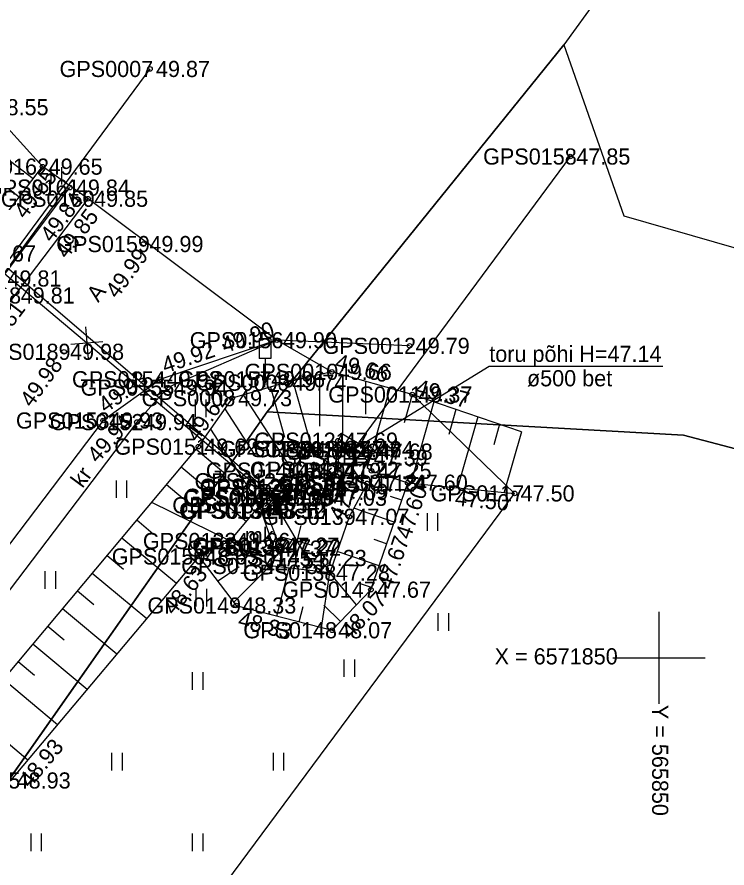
# Model space of a CAD drawing. Extents: x 563121 to 567545, y 6570841 to 6581299.
# Drawn here: x 565822.17 to 565852.95, y 6571840.89 to 6571877.77 of the extents above; entities that cross this region are included whole.
import ezdxf

# ---------------------------------------------------------------- set-up
doc = ezdxf.new("R2010")
doc.units = 0
for name, color, linetype in [('HALJASTUS', 7, 'Continuous'), ('KORGUS-EH2000', 7, 'Continuous'), ('LIIKLUS', 7, 'Continuous'), ('MOOTKORG-EH2000', 7, 'Continuous'), ('MOOTMPUNKT', 7, 'Continuous'), ('MOOTNR', 7, 'Continuous'), ('MOOTPIIR', 7, 'Continuous'), ('PIIR', 7, 'Continuous'), ('RELJEEF', 7, 'Continuous'), ('SITRASS', 7, 'Continuous'), ('TEE', 7, 'Continuous'), ('TRUUP', 7, 'Continuous'), ('VORK', 7, 'Continuous')]:
    doc.layers.add(name, color=color, linetype=linetype)

msp = doc.modelspace()

# ---------------------------------------------------------------- linework, layer by layer
at = {"layer": 'HALJASTUS'}
for p, q in [((565823.642, 6571871.268), (565823.642, 6571870.507)), ((565824.097, 6571871.268), (565824.097, 6571870.507)), ((565829.901, 6571861.198), (565829.901, 6571860.437)), ((565830.357, 6571861.198), (565830.357, 6571860.437)), ((565826.469, 6571857.691), (565826.469, 6571856.93)), ((565826.924, 6571857.691), (565826.924, 6571856.93)), ((565839.953, 6571856.265), (565839.953, 6571855.504)), ((565840.408, 6571856.265), (565840.408, 6571855.504)), ((565823.385, 6571853.755), (565823.385, 6571852.994)), ((565823.84, 6571853.755), (565823.84, 6571852.994)), ((565829.929, 6571852.992), (565829.929, 6571852.231)), ((565830.384, 6571852.992), (565830.384, 6571852.231)), ((565840.42, 6571851.929), (565840.42, 6571851.168)), ((565840.875, 6571851.929), (565840.875, 6571851.168)), ((565836.343, 6571849.932), (565836.343, 6571849.171)), ((565836.798, 6571849.932), (565836.798, 6571849.171)), ((565829.772, 6571849.381), (565829.772, 6571848.619)), ((565830.228, 6571849.381), (565830.228, 6571848.619)), ((565826.272, 6571845.881), (565826.272, 6571845.119)), ((565826.728, 6571845.881), (565826.728, 6571845.119)), ((565833.272, 6571845.881), (565833.272, 6571845.119)), ((565833.728, 6571845.881), (565833.728, 6571845.119)), ((565822.772, 6571842.381), (565822.772, 6571841.619)), ((565823.228, 6571842.381), (565823.228, 6571841.619)), ((565829.772, 6571842.381), (565829.772, 6571841.619)), ((565830.228, 6571842.381), (565830.228, 6571841.619))]:
    msp.add_line(p, q, dxfattribs=at)
at = {"layer": 'KORGUS-EH2000'}
for centre in [(565823.283, 6571871.288), (565824.465, 6571870.379), (565825.255, 6571869.896), (565827.654, 6571867.933), (565833.439, 6571863.766), (565839.194, 6571863.521), (565824.215, 6571863.263), (565835.818, 6571862.396), (565828.407, 6571862.073), (565839.307, 6571861.411), (565825.907, 6571860.285), (565827.373, 6571860.217), (565830.033, 6571859.153), (565839.111, 6571857.59), (565843.741, 6571857.127), (565836.578, 6571856.112), (565830.061, 6571854.393), (565833.143, 6571853.982), (565837.516, 6571852.954), (565831.676, 6571852.267), (565835.834, 6571851.196)]:
    msp.add_circle(centre, 0.1, dxfattribs=at)
at = {"layer": 'LIIKLUS'}
for p, q in [((565832.677, 6571863.823), (565832.677, 6571862.973)), ((565833.177, 6571863.823), (565832.677, 6571863.823)), ((565833.177, 6571863.823), (565833.177, 6571862.973)), ((565833.177, 6571862.973), (565832.677, 6571862.973)), ((565832.927, 6571862.973), (565832.927, 6571862.073)), ((565833.177, 6571862.073), (565832.927, 6571862.073))]:
    msp.add_line(p, q, dxfattribs=at)
at = {"layer": 'MOOTMPUNKT'}
for centre in [(565827.937, 6571875.522), (565846.158, 6571871.726), (565823.283, 6571871.288), (565824.465, 6571870.379), (565825.255, 6571869.896), (565827.654, 6571867.933), (565833.439, 6571863.766), (565839.194, 6571863.521), (565824.215, 6571863.263), (565835.818, 6571862.396), (565828.407, 6571862.073), (565832.927, 6571862.073), (565833.848, 6571861.926), (565828.71, 6571861.712), (565831.495, 6571861.254), (565839.307, 6571861.411), (565825.907, 6571860.285), (565827.373, 6571860.217), (565836.087, 6571859.412), (565830.033, 6571859.153), (565834.809, 6571859.05), (565836.221, 6571859.042), (565836.771, 6571859.041), (565837.589, 6571858.936), (565837.376, 6571858.673), (565836.116, 6571858.151), (565834.07, 6571858.113), (565837.54, 6571858.106), (565833.65, 6571857.652), (565833.868, 6571857.415), (565837.347, 6571857.558), (565839.111, 6571857.59), (565833.88, 6571857.348), (565835.669, 6571857.187), (565843.741, 6571857.127), (565833.216, 6571856.912), (565833.338, 6571856.981), (565835.607, 6571856.94), (565832.684, 6571856.613), (565832.924, 6571856.373), (565832.978, 6571856.386), (565836.578, 6571856.112), (565831.411, 6571855.064), (565833.546, 6571854.861), (565833.311, 6571854.735), (565833.617, 6571854.78), (565830.061, 6571854.393), (565834.731, 6571854.328), (565833.143, 6571853.982), (565835.734, 6571853.689), (565837.516, 6571852.954), (565831.676, 6571852.267), (565835.834, 6571851.196)]:
    msp.add_circle(centre, 0.1, dxfattribs=at)
at = {"layer": 'MOOTPIIR'}
msp.add_lwpolyline([(565813.701, 6571814.393), (565829.693, 6571838.184), (565843.741, 6571857.127), (565839.301, 6571861.413), (565835.818, 6571862.396), (565833.439, 6571863.766), (565825.255, 6571869.896), (565823.283, 6571871.288), (565820.939, 6571873.864)], dxfattribs=at)
at = {"layer": 'PIIR'}
for points in [[(566138.88, 6572289.1), (566071.95, 6572189.53), (566056.92, 6572168.48), (566043.44, 6572149.59), (566020.47, 6572117.41), (565845.87, 6571876.56), (565833.02, 6571860.66), (565803.59, 6571818.77), (565766.84, 6571778.8), (565712.27, 6571733.72), (565636.36, 6571689.97), (565561.65, 6571658.97), (565400, 6571600), (565315, 6571572), (565230, 6571552), (564980, 6571552), (564921.56, 6571543.26)], [(566222.72, 6571643.14), (566175.38, 6571706.88), (566160.83, 6571717.7), (566147.53, 6571725.81), (566110.96, 6571742.32), (566089.86, 6571753.57), (566023.53, 6571796.39), (565973.49, 6571828.72), (565960.44, 6571833.78), (565901.01, 6571846.54), (565851.06, 6571859.65), (565833.02, 6571860.66), (565845.87, 6571876.56), (565848.48, 6571869.16), (565894.21, 6571855.99), (565956.81, 6571842.83), (565976.14, 6571837.09), (566103.84, 6571756.13), (566111.74, 6571748.71), (566152.2, 6571729.75), (566168.46, 6571720.07), (566178.83, 6571711.76), (566186.69, 6571703.16)]]:
    msp.add_lwpolyline(points, dxfattribs=at)
msp.add_lwpolyline([(565833.02, 6571860.66), (565851.06, 6571859.65), (565901.01, 6571846.54), (565960.44, 6571833.78), (565973.49, 6571828.72), (566023.53, 6571796.39), (566089.86, 6571753.57), (566110.96, 6571742.32), (566147.53, 6571725.81), (566160.83, 6571717.7), (565835.49, 6571610.61), (565803.59, 6571818.77)], close=True, dxfattribs=at)
at = {"layer": 'RELJEEF'}
for p, q in [((565822.269, 6571869.967), (565819.219, 6571872.307)), ((565822.878, 6571870.76), (565821.648, 6571871.704)), ((565834.125, 6571861.992), (565834.992, 6571858.924)), ((565835.283, 6571862.268), (565835.283, 6571860.044)), ((565836.283, 6571862.264), (565836.283, 6571859.684)), ((565837.283, 6571861.982), (565837.283, 6571860.554)), ((565833.16, 6571861.729), (565833.774, 6571859.557)), ((565838.339, 6571861.684), (565837.349, 6571858.242)), ((565831.981, 6571861.393), (565834.085, 6571858.133)), ((565839.301, 6571861.413), (565838.949, 6571860.187)), ((565840.249, 6571861.091), (565839.238, 6571857.577)), ((565831.176, 6571860.795), (565832.451, 6571858.82)), ((565841.197, 6571860.768), (565840.885, 6571859.684)), ((565842.145, 6571860.446), (565841.261, 6571857.375)), ((565843.092, 6571860.123), (565842.837, 6571859.236)), ((565830.558, 6571859.908), (565832.695, 6571856.598)), ((565844.04, 6571859.801), (565843.284, 6571857.173)), ((565829.937, 6571859.039), (565831.224, 6571857.959)), ((565829.937, 6571859.039), (565830.645, 6571858.445)), ((565829.295, 6571858.272), (565832.115, 6571855.906)), ((565828.652, 6571857.506), (565829.359, 6571856.913)), ((565838.848, 6571856.827), (565838.369, 6571856.992)), ((565828.009, 6571856.74), (565831.411, 6571855.064)), ((565838.523, 6571855.881), (565836.775, 6571856.482)), ((565827.366, 6571855.974), (565828.074, 6571855.38)), ((565826.724, 6571855.208), (565829.083, 6571853.229)), ((565838.197, 6571854.935), (565837.654, 6571855.123)), ((565837.872, 6571853.99), (565836.056, 6571854.615)), ((565826.081, 6571854.442), (565826.788, 6571853.849)), ((565830.868, 6571853.33), (565831.809, 6571853.962)), ((565831.569, 6571852.408), (565833.143, 6571853.982)), ((565833.441, 6571851.812), (565833.976, 6571853.888)), ((565825.438, 6571853.676), (565827.795, 6571851.698)), ((565835.378, 6571851.313), (565835.734, 6571853.689)), ((565836.891, 6571852.3), (565835.734, 6571853.689)), ((565837.547, 6571853.044), (565836.975, 6571853.241)), ((565824.795, 6571852.91), (565825.502, 6571852.317)), ((565824.153, 6571852.144), (565826.508, 6571850.168)), ((565834.409, 6571851.563), (565834.58, 6571852.226)), ((565836.199, 6571851.577), (565835.467, 6571852.278)), ((565823.51, 6571851.378), (565824.216, 6571850.785)), ((565822.867, 6571850.612), (565825.22, 6571848.637)), ((565822.225, 6571849.845), (565822.93, 6571849.253)), ((565821.582, 6571849.079), (565823.933, 6571847.107)), ((565820.296, 6571847.547), (565822.646, 6571845.576))]:
    msp.add_line(p, q, dxfattribs=at)
for points in [[(565800.51, 6571847.744), (565800.538, 6571847.723), (565801.66, 6571847.165), (565807.743, 6571853.735), (565820.396, 6571867.526), (565823.283, 6571871.288)], [(565844.04, 6571859.801), (565839.307, 6571861.411), (565835.818, 6571862.396), (565833.848, 6571861.926), (565831.495, 6571861.254), (565830.033, 6571859.153), (565819.486, 6571846.581), (565806.328, 6571829.271), (565803.644, 6571823.76)], [(565836.087, 6571859.412), (565836.116, 6571858.151)], [(565837.376, 6571858.673), (565837.349, 6571858.242), (565837.54, 6571858.106), (565839.111, 6571857.59), (565843.741, 6571857.127)], [(565831.411, 6571855.064), (565830.061, 6571854.393), (565831.676, 6571852.267), (565835.834, 6571851.196), (565837.516, 6571852.954), (565839.111, 6571857.59)], [(565837.347, 6571857.558), (565836.578, 6571856.112), (565835.734, 6571853.689), (565833.143, 6571853.982)], [(565830.061, 6571854.393), (565821.897, 6571844.686), (565807.174, 6571828.74), (565803.644, 6571823.76)]]:
    msp.add_lwpolyline(points, dxfattribs=at)
at = {"layer": 'SITRASS'}
for p, q in [((565825.142, 6571864.347), (565825.262, 6571862.952)), ((565824.505, 6571863.589), (565825.899, 6571863.71)), ((565834.478, 6571855.738), (565834.125, 6571854.384)), ((565833.624, 6571855.238), (565834.979, 6571854.885))]:
    msp.add_line(p, q, dxfattribs=at)
for points in [[(565827.937, 6571875.522), (565819.589, 6571864.258), (565813.931, 6571856.898), (565805.842, 6571846.363), (565798.797, 6571837.231), (565791.619, 6571827.726), (565784.171, 6571818.664)], [(565814.466, 6571872.061), (565816.874, 6571870.651), (565833.216, 6571856.912), (565834.731, 6571854.328)], [(565783.542, 6571819.443), (565787.788, 6571824.729), (565795.262, 6571834.475), (565801.765, 6571842.375), (565808.482, 6571851.414), (565811.284, 6571854.993), (565814.22, 6571858.353), (565815.357, 6571859.794), (565816.36, 6571859.39), (565822.04, 6571867.24), (565823.485, 6571869.196), (565824.591, 6571870.729)]]:
    msp.add_lwpolyline(points, dxfattribs=at)
at = {"layer": 'TEE'}
for points in [[(565784.347, 6571818.115), (565798.874, 6571835.854), (565810.584, 6571851.423), (565821.499, 6571866.441), (565824.465, 6571870.379)], [(565785.017, 6571817.401), (565799.254, 6571835.472), (565811.058, 6571850.919), (565822.074, 6571865.705), (565825.255, 6571869.896)], [(565839.194, 6571863.521), (565833.439, 6571863.766), (565828.407, 6571862.073), (565825.907, 6571860.285), (565817.092, 6571848.675), (565804.137, 6571831.188), (565797.898, 6571823.166), (565798.048, 6571821.994), (565800.139, 6571818.615), (565801.078, 6571813.504), (565797.777, 6571812.08), (565794.654, 6571813.34), (565791.141, 6571814.563), (565789.374, 6571812.429)], [(565833.439, 6571863.766), (565828.71, 6571861.712), (565827.373, 6571860.217), (565817.957, 6571847.828), (565804.535, 6571830.717), (565801.583, 6571826.805), (565800.955, 6571825.15), (565801.025, 6571821.866), (565801.467, 6571818.976), (565802.633, 6571814.638), (565802.718, 6571813.36), (565804.674, 6571805.685), (565807.231, 6571788.975), (565811.315, 6571764.792), (565815.474, 6571739.551), (565820.53, 6571709.209), (565821.038, 6571705.752), (565823.803, 6571687.466)], [(565835.669, 6571857.187), (565836.116, 6571858.151), (565834.809, 6571859.05), (565834.07, 6571858.113), (565833.65, 6571857.652)], [(565833.311, 6571854.735), (565833.143, 6571853.982), (565831.411, 6571855.064), (565832.686, 6571856.589)]]:
    msp.add_lwpolyline(points, dxfattribs=at)
at = {"layer": 'TRUUP'}
for p, q in [((565846.158, 6571871.726), (565836.76, 6571859.026)), ((565817.145, 6571870.856), (565833.415, 6571856.915)), ((565836.82, 6571859.107), (565836.05, 6571858.992)), ((565836.071, 6571858.851), (565836.05, 6571858.992)), ((565836.056, 6571858.95), (565836.071, 6571858.995)), ((565836.76, 6571859.026), (565836.061, 6571858.922)), ((565836.065, 6571858.895), (565836.099, 6571858.999)), ((565836.077, 6571858.852), (565836.127, 6571859.003)), ((565836.104, 6571858.856), (565836.154, 6571859.007)), ((565836.132, 6571858.86), (565836.182, 6571859.012)), ((565836.16, 6571858.864), (565836.21, 6571859.016)), ((565836.187, 6571858.868), (565836.237, 6571859.02)), ((565836.215, 6571858.873), (565836.265, 6571859.024)), ((565836.243, 6571858.877), (565836.293, 6571859.028)), ((565836.27, 6571858.881), (565836.32, 6571859.032)), ((565836.298, 6571858.885), (565836.348, 6571859.036)), ((565836.326, 6571858.889), (565836.376, 6571859.041)), ((565836.354, 6571858.893), (565836.403, 6571859.045)), ((565836.381, 6571858.897), (565836.431, 6571859.049)), ((565836.409, 6571858.902), (565836.459, 6571859.053)), ((565836.437, 6571858.906), (565836.486, 6571859.057)), ((565836.464, 6571858.91), (565836.514, 6571859.061)), ((565836.492, 6571858.914), (565836.542, 6571859.065)), ((565836.52, 6571858.918), (565836.57, 6571859.07)), ((565836.547, 6571858.922), (565836.597, 6571859.074)), ((565836.575, 6571858.926), (565836.625, 6571859.078)), ((565836.603, 6571858.931), (565836.653, 6571859.082)), ((565836.63, 6571858.935), (565836.68, 6571859.086)), ((565836.658, 6571858.939), (565836.708, 6571859.09)), ((565836.686, 6571858.943), (565836.736, 6571859.094)), ((565836.704, 6571858.919), (565836.763, 6571859.099)), ((565836.712, 6571858.864), (565836.791, 6571859.103)), ((565836.72, 6571858.809), (565836.819, 6571859.107)), ((565836.729, 6571858.754), (565836.828, 6571859.054)), ((565836.737, 6571858.699), (565836.836, 6571858.999)), ((565836.864, 6571858.327), (565836.76, 6571859.026)), ((565836.935, 6571858.337), (565836.82, 6571859.107)), ((565836.7, 6571858.945), (565836.071, 6571858.851)), ((565836.794, 6571858.316), (565836.7, 6571858.945)), ((565836.745, 6571858.644), (565836.844, 6571858.944)), ((565836.753, 6571858.589), (565836.852, 6571858.889)), ((565836.762, 6571858.534), (565836.861, 6571858.834)), ((565836.77, 6571858.479), (565836.869, 6571858.779)), ((565836.778, 6571858.424), (565836.877, 6571858.725)), ((565836.786, 6571858.369), (565836.885, 6571858.67)), ((565836.794, 6571858.316), (565836.935, 6571858.337)), ((565836.795, 6571858.316), (565836.893, 6571858.615)), ((565836.823, 6571858.32), (565836.902, 6571858.56)), ((565836.85, 6571858.325), (565836.91, 6571858.505)), ((565836.878, 6571858.329), (565836.918, 6571858.45)), ((565836.906, 6571858.333), (565836.926, 6571858.395)), ((565834.115, 6571857.041), (565833.339, 6571856.981)), ((565833.339, 6571856.981), (565833.399, 6571856.205)), ((565833.629, 6571856.86), (565833.339, 6571856.98)), ((565833.574, 6571856.856), (565833.341, 6571856.952)), ((565833.519, 6571856.852), (565833.343, 6571856.924)), ((565833.493, 6571856.835), (565833.345, 6571856.896)), ((565833.495, 6571856.807), (565833.348, 6571856.868)), ((565833.497, 6571856.779), (565833.35, 6571856.84)), ((565833.499, 6571856.752), (565833.352, 6571856.812)), ((565833.502, 6571856.724), (565833.354, 6571856.784)), ((565833.685, 6571856.865), (565833.392, 6571856.985)), ((565834.12, 6571856.97), (565833.415, 6571856.915)), ((565833.415, 6571856.915), (565833.47, 6571856.21)), ((565833.74, 6571856.869), (565833.448, 6571856.989)), ((565834.126, 6571856.899), (565833.492, 6571856.85)), ((565833.492, 6571856.85), (565833.541, 6571856.216)), ((565833.796, 6571856.873), (565833.503, 6571856.993)), ((565833.851, 6571856.877), (565833.558, 6571856.998)), ((565833.906, 6571856.882), (565833.614, 6571857.002)), ((565833.962, 6571856.886), (565833.669, 6571857.006)), ((565834.017, 6571856.89), (565833.724, 6571857.01)), ((565834.072, 6571856.895), (565833.78, 6571857.015)), ((565834.126, 6571856.9), (565833.835, 6571857.019)), ((565834.124, 6571856.928), (565833.891, 6571857.023)), ((565834.121, 6571856.955), (565833.946, 6571857.028)), ((565834.119, 6571856.983), (565834.001, 6571857.032)), ((565834.117, 6571857.011), (565834.057, 6571857.036)), ((565834.126, 6571856.899), (565834.115, 6571857.041)), ((565833.504, 6571856.696), (565833.356, 6571856.756)), ((565833.506, 6571856.668), (565833.358, 6571856.728)), ((565833.508, 6571856.64), (565833.361, 6571856.701)), ((565833.51, 6571856.612), (565833.363, 6571856.673)), ((565833.512, 6571856.584), (565833.365, 6571856.645)), ((565833.514, 6571856.556), (565833.367, 6571856.617)), ((565833.517, 6571856.528), (565833.369, 6571856.589)), ((565833.519, 6571856.5), (565833.371, 6571856.561)), ((565833.521, 6571856.472), (565833.373, 6571856.533)), ((565833.523, 6571856.445), (565833.376, 6571856.505)), ((565833.525, 6571856.417), (565833.378, 6571856.477)), ((565833.527, 6571856.389), (565833.38, 6571856.449)), ((565833.53, 6571856.361), (565833.382, 6571856.421)), ((565833.532, 6571856.333), (565833.384, 6571856.393)), ((565833.534, 6571856.305), (565833.386, 6571856.366)), ((565833.536, 6571856.277), (565833.389, 6571856.338)), ((565833.538, 6571856.249), (565833.391, 6571856.31)), ((565833.54, 6571856.221), (565833.393, 6571856.282)), ((565833.496, 6571856.212), (565833.395, 6571856.254)), ((565833.441, 6571856.208), (565833.397, 6571856.226)), ((565833.541, 6571856.216), (565833.399, 6571856.205))]:
    msp.add_line(p, q, dxfattribs=at)
for points in [[(565836.76, 6571859.026), (565842.637, 6571862.647), (565850.161, 6571862.647)], [(565833.82, 6571857.362), (565835.607, 6571856.94), (565835.669, 6571857.187), (565833.63, 6571857.63)], [(565832.686, 6571856.589), (565833.311, 6571854.735), (565833.546, 6571854.861), (565832.966, 6571856.419)]]:
    msp.add_lwpolyline(points, dxfattribs=at)
for points in [[(565836.087, 6571859.412), (565837.376, 6571858.673), (565837.542, 6571858.963), (565836.253, 6571859.701)], [(565832.924, 6571856.373), (565833.868, 6571857.415), (565833.63, 6571857.63), (565832.686, 6571856.589)]]:
    msp.add_lwpolyline(points, close=True, dxfattribs=at)
at = {"layer": 'VORK'}
for p, q in [((565850, 6571852), (565850, 6571848)), ((565848, 6571850), (565852, 6571850))]:
    msp.add_line(p, q, dxfattribs=at)

# ---------------------------------------------------------------- texts
at = {"layer": 'KORGUS-EH2000'}
for s, rotation, p in [(' 49.65', 52.4986, (565822.368, 6571868.773)), (' 49.84', 53.0097, (565823.524, 6571867.751)), (' 49.85', 52.8026, (565824.177, 6571867.044)), (' 49.99', 53.6272, (565826.359, 6571865.321)), (' 49.81', 52.8026, (565821, 6571863.045)), (' 49.90', 18.5916, (565830.929, 6571863.113)), (' 49.92', 18.5916, (565828.351, 6571862.239)), (' 49.66', 344.9636, (565835.662, 6571862.593)), (' 49.98', 53.6272, (565822.652, 6571860.602)), (' 49.93', 35.5806, (565825.806, 6571860.428)), (' 49.37', 344.9636, (565839.15, 6571861.486)), (' 49.62', 54.2232, (565829.843, 6571859.116)), (' 49.94', 48.1954, (565825.495, 6571858.205)), (' 47.07', 61.9592, (565836.13, 6571855.648)), (' 47.60', 71.0144, (565839.13, 6571854.847)), (' 47.50', 354.2948, (565840.877, 6571856.628)), (' 47.67', 71.0144, (565838.343, 6571852.669)), (' 47.53', 353.5586, (565832.95, 6571854.079)), (' 48.63', 49.9339, (565828.803, 6571851.609)), (' 48.07', 46.2856, (565836.467, 6571850.591)), (' 48.33', 345.5489, (565831.457, 6571851.42)), (' 48.93', 49.9339, (565822.567, 6571844.123))]:
    msp.add_text(s, height=0.7, rotation=rotation, dxfattribs=at).set_placement(p)
msp.add_text(' 49.79', height=0.7, dxfattribs=at).set_placement((565839.194, 6571863.171))
at = {"layer": 'MOOTKORG-EH2000'}
for s, p in [(' 49.87', (565827.937, 6571875.172)), (' 48.55', (565820.939, 6571873.514)), (' 47.85', (565846.158, 6571871.377)), (' 49.65', (565823.283, 6571870.938)), (' 49.84', (565824.465, 6571870.029)), (' 49.85', (565825.255, 6571869.547)), (' 49.99', (565827.654, 6571867.583)), (' 49.67', (565820.396, 6571867.176)), (' 49.81', (565821.499, 6571866.091)), (' 49.81', (565822.074, 6571865.355)), (' 49.90', (565833.439, 6571863.416)), (' 49.79', (565839.194, 6571863.171)), (' 49.98', (565824.215, 6571862.913)), (' 49.66', (565835.818, 6571862.046)), (' 49.92', (565828.407, 6571861.723)), (' 49.96', (565832.927, 6571861.723)), (' 49.94', (565828.71, 6571861.362)), (' 49.74', (565833.848, 6571861.576)), (' 49.73', (565831.495, 6571860.904)), (' 49.37', (565839.307, 6571861.061)), (' 49.93', (565825.907, 6571859.935)), (' 49.94', (565827.373, 6571859.867)), (' 47.69', (565836.087, 6571859.062)), (' 49.62', (565830.033, 6571858.803)), (' 48.01', (565834.809, 6571858.7)), (' 47.42', (565836.221, 6571858.691)), (' 47.64', (565836.771, 6571858.691)), (' 47.39', (565837.376, 6571858.323)), (' 47.68', (565837.589, 6571858.586)), (' 48.27', (565834.07, 6571857.763)), (' 47.22', (565836.116, 6571857.801)), (' 47.25', (565837.54, 6571857.756)), (' 48.30', (565833.65, 6571857.302)), (' 47.24', (565837.347, 6571857.208)), (' 47.60', (565839.111, 6571857.24)), (' 48.51', (565833.868, 6571857.065)), (' 48.06', (565833.88, 6571856.998)), (' 47.09', (565835.669, 6571856.837)), (' 47.00', (565833.216, 6571856.562)), (' 46.98', (565833.338, 6571856.631)), (' 47.03', (565835.607, 6571856.59)), (' 47.50', (565843.741, 6571856.777)), (' 48.54', (565832.684, 6571856.263)), (' 48.52', (565832.924, 6571856.023)), (' 48.10', (565832.978, 6571856.036)), (' 47.07', (565836.578, 6571855.763)), (' 48.26', (565831.411, 6571854.714)), (' 47.37', (565833.311, 6571854.385)), (' 47.27', (565833.546, 6571854.511)), (' 47.22', (565833.617, 6571854.43)), (' 48.63', (565830.061, 6571854.043)), (' 47.23', (565834.731, 6571853.978)), (' 47.53', (565833.143, 6571853.632)), (' 47.28', (565835.734, 6571853.339)), (' 47.67', (565837.516, 6571852.604)), (' 48.33', (565831.676, 6571851.917)), (' 48.07', (565835.834, 6571850.846)), (' 48.93', (565821.897, 6571844.336))]:
    msp.add_text(s, height=0.7, dxfattribs=at).set_placement(p)
at = {"layer": 'MOOTNR'}
for s, p in [('GPS0007 ', (565824.018, 6571875.172)), ('GPS0158 ', (565842.378, 6571871.377)), ('GPS0162 ', (565819.503, 6571870.938)), ('GPS0161 ', (565820.826, 6571870.029)), ('GPS0160 ', (565821.476, 6571869.547)), ('GPS0159 ', (565823.875, 6571867.583)), ('GPS0188 ', (565818.294, 6571865.355)), ('GPS0156 ', (565829.66, 6571863.416)), ('GPS0012 ', (565835.414, 6571863.171)), ('GPS0189 ', (565820.435, 6571862.913)), ('GPS0010 ', (565832.039, 6571862.046)), ('GPS0154 ', (565824.557, 6571861.723)), ('GPS0157 ', (565829.148, 6571861.723)), ('GPS0155 ', (565824.93, 6571861.362)), ('GPS0009 ', (565829.928, 6571861.576)), ('GPS0008 ', (565827.575, 6571860.904)), ('GPS0011 ', (565835.667, 6571861.061)), ('GPS0153 ', (565822.128, 6571859.935)), ('GPS0152 ', (565823.593, 6571859.867)), ('GPS0121 ', (565832.447, 6571859.062)), ('GPS0151 ', (565826.394, 6571858.803)), ('GPS0142 ', (565830.959, 6571858.7)), ('GPS0120 ', (565832.442, 6571858.691)), ('GPS0124 ', (565832.921, 6571858.691)), ('GPS0122 ', (565833.597, 6571858.323)), ('GPS0123 ', (565833.809, 6571858.586)), ('GPS0141 ', (565830.36, 6571857.763)), ('GPS0143 ', (565832.266, 6571857.801)), ('GPS0119 ', (565833.9, 6571857.756)), ('GPS0127 ', (565829.87, 6571857.302)), ('GPS0140 ', (565833.498, 6571857.208)), ('GPS0118 ', (565835.471, 6571857.24)), ('GPS0128 ', (565830.088, 6571857.065)), ('GPS0129 ', (565830.1, 6571856.998)), ('GPS0126 ', (565831.89, 6571856.837)), ('GPS0146 ', (565829.367, 6571856.562)), ('GPS0144 ', (565829.418, 6571856.631)), ('GPS0125 ', (565831.827, 6571856.59)), ('GPS0117 ', (565840.101, 6571856.777)), ('GPS0132 ', (565828.904, 6571856.263)), ('GPS0130 ', (565829.198, 6571856.036)), ('GPS0131 ', (565829.284, 6571856.023)), ('GPS0139 ', (565832.798, 6571855.763)), ('GPS0133 ', (565827.631, 6571854.714)), ('GPS0135 ', (565829.531, 6571854.385)), ('GPS0136 ', (565829.766, 6571854.511)), ('GPS0137 ', (565829.837, 6571854.43)), ('GPS0150 ', (565826.281, 6571854.043)), ('GPS0145 ', (565830.881, 6571853.978)), ('GPS0134 ', (565829.293, 6571853.632)), ('GPS0138 ', (565831.954, 6571853.339)), ('GPS0147 ', (565833.666, 6571852.604)), ('GPS0149 ', (565827.826, 6571851.917)), ('GPS0148 ', (565831.985, 6571850.846)), ('GPS0115 ', (565818.257, 6571844.336))]:
    msp.add_text(s, height=0.7, dxfattribs=at).set_placement(p)
at = {"layer": 'TEE'}
for s, rotation, p in [('A', 52.5067, (565825.694, 6571865.374)), ('kr', 53.5871, (565825.011, 6571857.321))]:
    msp.add_text(s, height=0.7, rotation=rotation, dxfattribs=at).set_placement(p)
for p in [(565834.612, 6571857.701), (565832.046, 6571854.953)]:
    msp.add_text('mk', height=0.7, dxfattribs=at).set_placement(p)
at = {"layer": 'TRUUP'}
for s, p in [('toru põhi H=47.14', (565842.644, 6571862.824)), ('ø500 bet', (565844.278, 6571861.767))]:
    msp.add_text(s, height=0.7, dxfattribs=at).set_placement(p)
at = {"layer": 'VORK'}
msp.add_text('X = 6571850', height=0.7, dxfattribs=at).set_placement((565842.878, 6571849.715))
msp.add_text('Y = 565850 ', height=0.7, rotation=270, dxfattribs=at).set_placement((565849.703, 6571847.965))

doc.saveas('drawing.dxf')
